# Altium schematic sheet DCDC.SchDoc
size A4; DocumentNumber: 2; SheetNumber: 2; SheetTotal: 6; PageSetup: Record=PageOptions|CenterHorizontal=True|CenterVertical=True|PrintScale=0.70|XCorrection=1.00|YCorrection=1.00|PrintKind=0|BorderSize=5000000|LeftOffset=5|BottomOffset=0|Orientation=1|PaperLength=1000|PaperWidth=1000|Scale=100|PaperSource=7|PrintQuality=-4|MediaType=1|DitherType=10|PaperKind=A4|PrintScaleMode=1
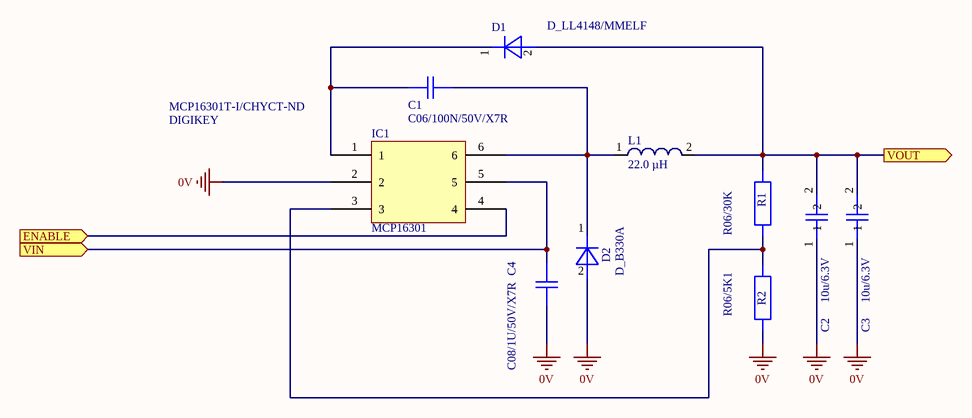
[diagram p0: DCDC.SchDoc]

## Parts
C1  C06/100N/50V/X7R  [C02X60Y0A1]
C2  value 10u/6.3V  [C02X75Y0A1]  (hidden comment: C08/10U)
C3  value 10u/6.3V  [C02X75Y0A1]  (hidden comment: C08/10U)
C4  C08/1U/50V/X7R  [C02X75Y0A1]
D1  D_LL4148/MMELF  [D02X125Y0A0]
D2  D_B330A  [D02X157Y0A0]
IC1  MCP16301  Supplier 1: DIGIKEY  Supplier Part Number 1: MCP16301T-I/CHYCT-ND  [SOT23-6_L]
L1  22.0 µH  [WE-TPC 3816, S]
R1  R06/30K  [R02X60Y0A0]
R2  R06/5K1  [R02X60Y0A0]

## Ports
ENABLE (in), VIN (in), VOUT (out)

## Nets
0V: C2.1 C3.1 C4.1 D2.2 IC1.2 R2.1
ENABLE: IC1.4 ; port ENABLE
VIN: C4.2 IC1.5 ; port VIN
VOUT: C2.2 C3.2 D1.2(A) L1.2 R1.2 ; port VOUT
NetC1_1: C1.1 D2.1 IC1.6 L1.1
NetC1_2: C1.2 D1.1(K) IC1.1
NetIC1_3: IC1.3 R1.1 R2.2

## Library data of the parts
C1 = C06/100N/50V/X7R: CHIP-CAP. 0.1UF 50V 10% X7R 0603; Manufacturer Part Number 1: GRM188R71H104KA93D; MFG.#1: MURATA; Geometry.Height: 1.00 mm; SUPP.#1: DIGIKEY; SUPP.ART.#1: 490-1519-1-ND
C2 C3 = C08/10U/6V3/X5R: CHIP CAP 0805  10U 6V3 X5R; Geometry.Height: 0.99mm; TYPE: GRM21BR60J106KE19L; MFG.#1: MURATA; SUPP.#1: DIGIKEY; SUPP.ART.#1: 490-1717-6-ND
C4 = C08/1U/50V/X7R: CHIP-CAP. 0805 1UF 50V X7R; Manufacturer Part Number 1: GRM21BR71H105KA12L; VALUE: 1u/50V; MFG.#1: MURATA; Geometry.Height: 1.25mm; SUPP.#1: FARNELL; SUPP.ART.#1: 1735541
D1 = D_LL4148/MMELF: DIODE MINI MELF 75V 0.2A; Manufacturer Part Number 1: LL4148; VALUE: 75V/0A2; MFG.#1: ITT; Geometry.Height: 3.6mm; GR: D; SUPP.#1: BUERKLIN; SUPP.ART.#1: 24 S 3460
D2 = D_B330A: SCHOTTKY  BARRIER DIODE; Manufacturer Part Number 1: B330A; VALUE: 30V/3A; MFG.#1: DIODES INCORPORATED; Geometry.Height: 2.62mm; SUPP.#1: FARNELL; SUPP.ART.#1: 759-9511
IC1 = mcp16301: STEP DOWN CONVERTER; Manufacturer Part Number 1: MCP16301T-I/CH; Geometry.Height: 1.75mm; MFG.#1: MICROCHIP
L1 = WE-TPC 3816, S, 744031220: SMD Shielded Tiny Power Inductor WE-TPC, L=22.0 µH; PART DESCE: SMD SHIELDED INDUCTOR WE-TPC  22.0 µH; MFG.#1: WUERTH; VALUE: 22yH; Geometry.Height: 3.0mm
R1 = R06/30K: CHIP RESISTOR 30K OHM 0.063W 1% 0603 SMD; Manufacturer Part Number 1: MC 0.063W 0603 1% 30K; MFG.#1: MULTICOMP; Geometry.Height: 0.45mm; SUPP.#1: FARNELL; SUPP.ART.#1: 9330984
R2 = R06/5K1: CHIP RESISTOR 5K1 OHM 0.063W 1% 0603 SMD; Manufacturer Part Number 1: MC 0.063W 0603 1% 5K1; MFG.#1: MULTICOMP; Geometry.Height: 0.45mm; SUPP.#1: FARNELL; SUPP.ART.#1: 9331301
